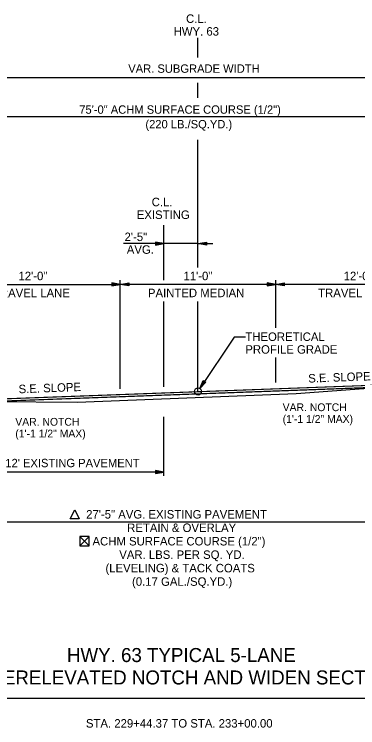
# Model space of a CAD drawing. Extents: x 1461846 to 1462006, y 1686171 to 1686805.
# Drawn here: x 1461914.2 to 1461938.5, y 1686330.5 to 1686380.9 of the extents above; entities that cross this region are included whole.
import ezdxf

# ---------------------------------------------------------------- set-up
doc = ezdxf.new("R2010")
doc.units = 0
for name, color, linetype in [('10', 7, 'Continuous'), ('12', 7, 'Continuous'), ('19', 7, 'Continuous'), ('20', 7, 'Continuous'), ('3', 7, 'Continuous'), ('42', 7, 'Continuous'), ('R_Draft', 7, 'Continuous')]:
    doc.layers.add(name, color=color, linetype=linetype)

msp = doc.modelspace()

# ---------------------------------------------------------------- linework, layer by layer
at = {"layer": '10'}
for p, q in [((1461918.83, 1686343.983), (1461919.471, 1686343.341)), ((1461919.471, 1686343.983), (1461918.83, 1686343.341))]:
    msp.add_line(p, q, dxfattribs=at)
for points in [[(1461918.787, 1686345.233), (1461918.146, 1686345.233), (1461918.467, 1686345.874), (1461918.787, 1686345.233)], [(1461919.222, 1686343.341), (1461919.471, 1686343.341), (1461919.471, 1686343.983), (1461918.83, 1686343.983), (1461918.83, 1686343.341), (1461919.211, 1686343.341)]]:
    msp.add_lwpolyline(points, dxfattribs=at)
at = {"layer": '19'}
for p, q in [((1461927.18, 1686377.823), (1461927.18, 1686379.214)), ((1461927.18, 1686374.977), (1461927.18, 1686376.023)), ((1461927.18, 1686362.992), (1461927.18, 1686372.017))]:
    msp.add_line(p, q, dxfattribs=at)
msp.add_lwpolyline([(1461964.762, 1686355.458), (1461960.956, 1686355.318), (1461940.777, 1686354.571), (1461921.639, 1686353.863), (1461914.019, 1686353.581), (1461903.26, 1686353.183), (1461897.595, 1686352.973), (1461895.595, 1686352.893), (1461889.595, 1686352.653), (1461889.595, 1686352.653), (1461889.595, 1686352.653), (1461889.68, 1686352.823), (1461889.68, 1686352.823), (1461889.68, 1686352.823), (1461895.545, 1686353.058), (1461903.665, 1686353.365), (1461913.994, 1686353.747), (1461921.643, 1686354.03), (1461940.732, 1686354.736), (1461960.903, 1686355.482), (1461964.68, 1686355.622)], close=True, dxfattribs=at)
at = {"layer": '20'}
for p, q in [((1461976.425, 1686376.393), (1461879.904, 1686376.393)), ((1461964.68, 1686373.624), (1461889.68, 1686373.624))]:
    msp.add_line(p, q, dxfattribs=at)
at = {"layer": '3'}
msp.add_line((1461946.153, 1686332.55), (1461908.207, 1686332.55), dxfattribs=at)
at = {"layer": 'R_Draft'}
for p, q in [((1461924.763, 1686362.092), (1461924.763, 1686365.971)), ((1461924.763, 1686364.678), (1461921.92, 1686364.678)), ((1461924.163, 1686364.783), (1461924.163, 1686364.573)), ((1461924.763, 1686364.678), (1461924.163, 1686364.783)), ((1461924.603, 1686364.693), (1461924.163, 1686364.728)), ((1461924.163, 1686364.573), (1461924.763, 1686364.678)), ((1461924.163, 1686364.623), (1461924.603, 1686364.663)), ((1461927.18, 1686364.678), (1461924.763, 1686364.678)), ((1461927.18, 1686364.678), (1461927.78, 1686364.783)), ((1461927.78, 1686364.573), (1461927.18, 1686364.678)), ((1461927.18, 1686364.678), (1461928.233, 1686364.678)), ((1461927.34, 1686364.693), (1461927.78, 1686364.728)), ((1461927.78, 1686364.623), (1461927.34, 1686364.663)), ((1461927.78, 1686364.783), (1461927.78, 1686364.573)), ((1461921.08, 1686361.897), (1461921.08, 1686361.687)), ((1461921.68, 1686361.792), (1461921.08, 1686361.897)), ((1461921.52, 1686361.807), (1461921.08, 1686361.842)), ((1461921.68, 1686354.411), (1461921.68, 1686362.092)), ((1461921.68, 1686361.792), (1461922.28, 1686361.897)), ((1461921.84, 1686361.807), (1461922.28, 1686361.842)), ((1461922.28, 1686361.897), (1461922.28, 1686361.687)), ((1461932.08, 1686361.897), (1461932.08, 1686361.687)), ((1461932.68, 1686361.792), (1461932.08, 1686361.897)), ((1461932.52, 1686361.807), (1461932.08, 1686361.842)), ((1461932.68, 1686358.734), (1461932.68, 1686362.092)), ((1461932.68, 1686361.792), (1461933.28, 1686361.897)), ((1461932.84, 1686361.807), (1461933.28, 1686361.842)), ((1461933.28, 1686361.897), (1461933.28, 1686361.687)), ((1461909.68, 1686361.792), (1461921.68, 1686361.792)), ((1461921.08, 1686361.687), (1461921.68, 1686361.792)), ((1461921.08, 1686361.737), (1461921.52, 1686361.777)), ((1461922.28, 1686361.687), (1461921.68, 1686361.792)), ((1461932.68, 1686361.792), (1461921.68, 1686361.792)), ((1461922.28, 1686361.737), (1461921.84, 1686361.777)), ((1461932.08, 1686361.687), (1461932.68, 1686361.792)), ((1461932.08, 1686361.737), (1461932.52, 1686361.777)), ((1461933.28, 1686361.687), (1461932.68, 1686361.792)), ((1461944.68, 1686361.792), (1461932.68, 1686361.792)), ((1461933.28, 1686361.737), (1461932.84, 1686361.777)), ((1461924.763, 1686354.564), (1461924.763, 1686360.592)), ((1461927.18, 1686354.235), (1461927.18, 1686360.592)), ((1461932.68, 1686354.878), (1461932.68, 1686356.633)), ((1461927.311, 1686354.448), (1461927.557, 1686355.005)), ((1461927.73, 1686354.889), (1461927.311, 1686354.448)), ((1461927.39, 1686354.586), (1461927.598, 1686354.971)), ((1461927.69, 1686354.912), (1461927.413, 1686354.574)), ((1461927.557, 1686355.005), (1461927.73, 1686354.889)), ((1461924.763, 1686348.28), (1461924.763, 1686352.449)), ((1461912.758, 1686348.547), (1461924.763, 1686348.547)), ((1461924.163, 1686348.65), (1461924.163, 1686348.44)), ((1461924.763, 1686348.545), (1461924.163, 1686348.65)), ((1461924.603, 1686348.56), (1461924.163, 1686348.595)), ((1461924.163, 1686348.44), (1461924.763, 1686348.545)), ((1461924.163, 1686348.49), (1461924.603, 1686348.53)), ((1461912.763, 1686345.033), (1461940.18, 1686345.033))]:
    msp.add_line(p, q, dxfattribs=at)
for points in [[(1461930.532, 1686358.079), (1461929.727, 1686358.079), (1461927.311, 1686354.448)], [(1461897.68, 1686353.143), (1461927.18, 1686354.235), (1461956.68, 1686355.326)], [(1461897.68, 1686352.976), (1461927.18, 1686354.068), (1461956.68, 1686355.159)], [(1461847.362, 1686353.269), (1461867.322, 1686352.565), (1461882.06, 1686349.033), (1461884.194, 1686348.879), (1461888.604, 1686349.011), (1461896.486, 1686349.242), (1461912.763, 1686353.534), (1461918.661, 1686353.486), (1461934.122, 1686354.079), (1461940.18, 1686354.549), (1461946.68, 1686353.887), (1461962.552, 1686349.481)], [(1461897.68, 1686352.976), (1461918.68, 1686353.753)], [(1461918.146, 1686345.233), (1461918.467, 1686345.874), (1461918.787, 1686345.233), (1461918.146, 1686345.233)]]:
    msp.add_lwpolyline(points, dxfattribs=at)
msp.add_circle((1461927.185, 1686354.232), 0.25, dxfattribs=at)

# ---------------------------------------------------------------- texts
at = {"layer": '10'}
for s, p in [('VAR. NOTCH', (1461933.168, 1686352.844)), ('VAR. NOTCH', (1461914.258, 1686351.815)), ('(1\'-1 1/2" MAX)', (1461933.168, 1686352.015)), ('(1\'-1 1/2" MAX)', (1461914.258, 1686350.986))]:
    msp.add_text(s, height=0.55, dxfattribs=at).set_placement(p)
for s, rotation, p in [('27\'-5" AVG. EXISTING PAVEMENT', 360, (1461919.27, 1686345.257)), ('RETAIN & OVERLAY', 360, (1461922.169, 1686344.307)), ('ACHM SURFACE COURSE (1/2")', 360, (1461919.717, 1686343.357)), ('VAR. LBS. PER SQ. YD.', 360, (1461921.611, 1686342.407)), ('(LEVELING) & TACK COATS', 360, (1461920.633, 1686341.457)), ('(0.17 GAL./SQ.YD.)', 360, (1461922.514, 1686340.507)), ('STA. 229+44.37 TO STA. 233+00.00', 0.0046, (1461919.254, 1686330.492))]:
    msp.add_text(s, height=0.6, rotation=rotation, dxfattribs=at).set_placement(p)
at = {"layer": '12'}
for s, p in [('HWY. 63 TYPICAL 5-LANE ', (1461917.911, 1686335.122)), ('SUPERELEVATED NOTCH AND WIDEN SECTION', (1461910.658, 1686333.537))]:
    msp.add_text(s, height=0.98999, rotation=0.0046, dxfattribs=at).set_placement(p)
at = {"layer": '42'}
for s, p in [('VAR. SUBGRADE WIDTH', (1461922.248, 1686376.743)), ('75\'-0" ACHM SURFACE COURSE (1/2")', (1461918.782, 1686373.849)), ('(220 LB./SQ.YD.)', (1461923.46, 1686372.816)), ("12' EXISTING PAVEMENT", (1461913.555, 1686348.885))]:
    msp.add_text(s, height=0.59001, dxfattribs=at).set_placement(p)
at = {"layer": 'R_Draft'}
for s, p in [('C.L.', (1461926.335, 1686380.266)), ('HWY. 63', (1461925.457, 1686379.366)), ('C.L.', (1461923.905, 1686367.316)), ('EXISTING', (1461922.849, 1686366.416)), ('2\'-5"', (1461921.985, 1686364.856)), ('AVG.', (1461922.143, 1686363.956)), ('12\'-0"', (1461914.482, 1686362.092)), ('11\'-0"', (1461926.152, 1686362.092)), ('12\'-0"', (1461937.482, 1686362.092)), ('TRAVEL LANE', (1461912.68, 1686360.892)), ('PAINTED MEDIAN', (1461923.639, 1686360.892)), ('TRAVEL LANE', (1461935.68, 1686360.892)), ('THEORETICAL', (1461930.528, 1686357.802)), ('PROFILE GRADE', (1461930.528, 1686356.902))]:
    msp.add_text(s, height=0.6, dxfattribs=at).set_placement(p)
for p in [(1461934.987, 1686354.856), (1461914.502, 1686354.102)]:
    msp.add_text('S.E. SLOPE', height=0.6, rotation=2.119, dxfattribs=at).set_placement(p)

doc.saveas('drawing.dxf')
